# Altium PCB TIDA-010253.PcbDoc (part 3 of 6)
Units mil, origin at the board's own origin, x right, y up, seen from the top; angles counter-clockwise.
Board outline 5525 x 6695 mil, 4 copper layers (Top Layer, Signal Layer 1, Signal Layer 2, Bottom Layer), stack 61.2 mil thick; 522 components, 391 nets, 1722 pads, 1048 vias.
Unrouted connection lines stored in the file: 22.
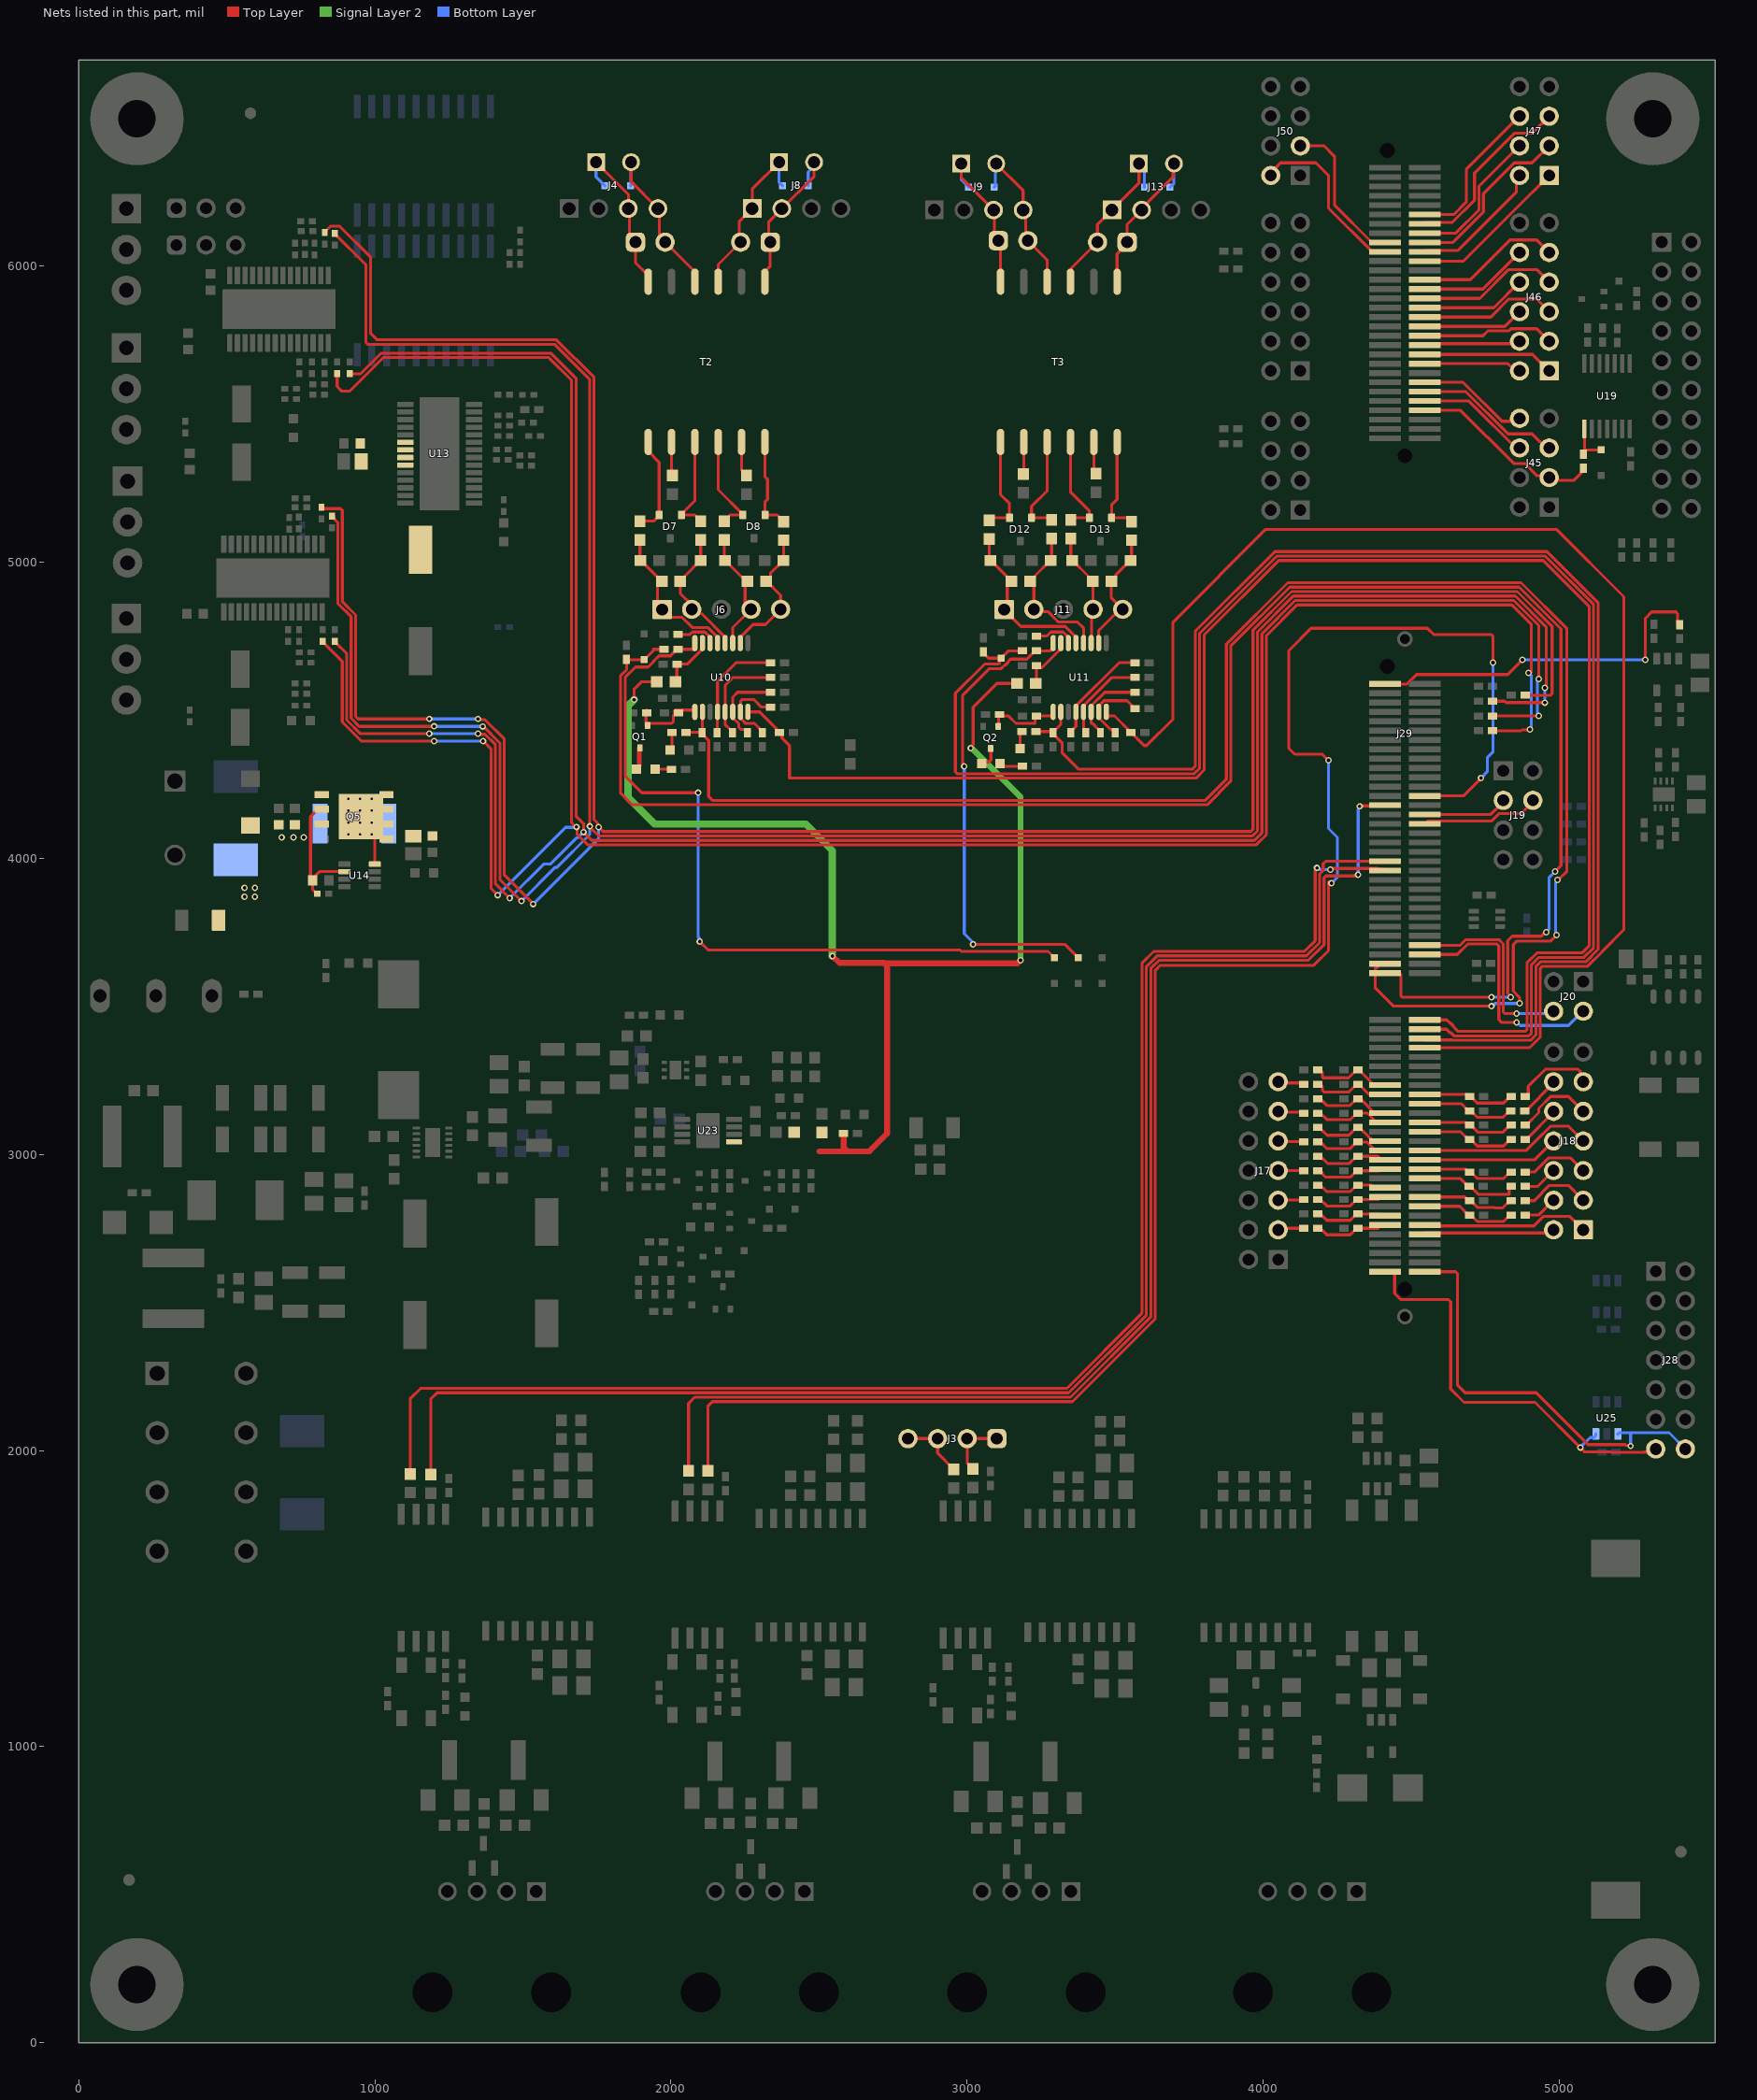
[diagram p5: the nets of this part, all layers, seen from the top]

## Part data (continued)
U28: library part CMP-0051906-3, "Automotive Catalog Dual Schmitt-Trigger Buffer, DCK0006A (SOT-SC70-6)", F @ Nom Voltage(Max)(Mhz)=150, Generic Part Number=SN74LVC2G17-Q1, ICC @ Nom Voltage(Max)(mA)=0.01, Manufacturer="Texas Instruments", Operating Temperature Range="-40 to 125 C", Rating=Automotive, tpd @ Nom Voltage(Max)(ns)=9.3,5.7,5.4,4.3, Voltage(Nom)(V)=1.8,2.5,3.3,5
U29: library part CMP-0035533-1, "Single Output LDO, 150 mA, Fixed 3.8 V Output, 2.7 to 10 V Input, with Low IQ, 5-pin SOT-23 (DBV), -40 to 125 degC, Green (RoHS & no Sb/Br)", Manufacturer="Texas Instruments"
U30: library part CMP-0089033-2, "Transformer Driver PMIC SOT-23-6", Manufacturer="Texas Instruments", Operating Temperature Range="-40°C to +125°C"
U31: library part CMP-0081937-2, "5-kVRMS Reinforced and Basic Isolated RS-485/RS-422 Transceiver With Robust-EMC, DW0016B (SOIC-16)", Alternate Manufacturer="Texas Instruments", Alternate PartNumber=ISO1410DW, Operating Temperature Range="-40 to 125 C"
U32: library part CMP-0087942-2, "Integrated Humidity and Temperature Digital Sensor", Manufacturer="Texas Instruments", Operating Temperature Range="-45°C to +150°C"
U33: library part CMP-0002019-2, "Asymmetrical TVS Diode for Extended Common-Mode RS-485, SOT-23", Manufacturer=Semtech, PartNumber=ESDS552, Supplier Part Number 1=SM712CT-ND
Y1: library part CMP-0004577-3, "Crystal, 32.768 kHz, 12.5pF, SMD", Frequency Stability=+/-20ppm, Frequency_Fixed=32.768kHz, Manufacturer=Epson, Supplier Part Number 1=SER2407CT-ND

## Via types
v1: diameter 22, hole 12, Top Layer to Bottom Layer, 944 vias
v2: diameter 19.68, hole 7.87, Top Layer to Bottom Layer, 76 vias
v3: diameter 19.68, hole 7.87, Top Layer to Bottom Layer, tented both sides, 16 vias
v4: diameter 22, hole 12, Top Layer to Bottom Layer, tented both sides, 12 vias

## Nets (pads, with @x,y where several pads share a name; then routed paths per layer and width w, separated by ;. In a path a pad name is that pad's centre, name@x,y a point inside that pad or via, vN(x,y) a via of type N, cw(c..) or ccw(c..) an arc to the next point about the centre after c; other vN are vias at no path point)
24V: C47.1 C48.1 C53.1 C59.1 Q5.5 Q5.6 Q5.7 Q5.8 Q5.9 R75.2 R84.2 U13.20 U13.21 U13.22 U13.23 U14.8 | length 104.1
  Top Layer w10: v2(990,4080) 1000,4070 U14.8@1000,3980
  other v2: 910,4080 950,4080 910,4120 950,4120 990,4120 910,4160 950,4160 990,4160 910,4200 950,4200 990,4200
24V_CONN: C50.1 C51.1 C52.1 D17.2 D36.2 F1.2 Q5.1 Q5.2 Q5.3 R75.1 R82.2 U14.2 | length 442.5
  Top Layer w10: C52.1@789.88,3925 789.88,3893.78 803.66,3880 R82.2@805.63,3880 ; Q5.2@820.5,4165 807.5,4165 782.5,4140 782.5,3927.38 784.88,3925 784.88,3925.98 813.31,3954.41 U14.2@897.64,3954.41
  other v1: 560,3870 595,3870 560,3900 595,3900 685,4070 725,4070 760,4070
"(9) HSEC_GPMC0_AD14": J29.169 J47.6 | length 521.8
  Top Layer w10: J29.169@4545,6173.35 4643.36,6173.35 4685,6214.99 4685,6325 J47.6@4865,6505
"(11) HSEC_GPMC0_AD0": J29.153 J46.10 | length 371.2
  Top Layer w10: J29.153@4545,5921.38 4741.38,5921.38 J46.10@4865,6045
"(11) HSEC_GPMC0_AD2": J29.155 J46.9 | length 493.4
  Top Layer w10: J29.155@4545,5952.87 4698.33,5952.87 4832.94,6087.48 4922.52,6087.48 J46.9@4965,6045
"(11) HSEC_GPMC0_AD4": J29.159 J47.1 | length 539.8
  Top Layer w10: J29.159@4545,6015.87 4675.79,6015.87 4847.4,6187.48 4847.48,6187.48 J47.1@4965,6305
"(13) HSEC_MII0_TXCLK": J29.129 J45.6 | length 389.8
  Top Layer w10: J29.129@4545,5543.43 4694.07,5543.43 4862.5,5375 J45.6@4865,5375
"(13) HSEC_MII0_TXD0": J29.131 J45.5 | length 502.8
  Top Layer w10: J29.131@4545,5574.92 4683.79,5574.92 4826.19,5432.52 4907.48,5432.52 J45.5@4965,5375
"(13) HSEC_MII0_TXD2": J29.133 J45.8 | length 374.4
  Top Layer w10: J29.133@4545,5606.42 4674.21,5606.42 4805.63,5475 J45.8@4865,5475
"(13) HSEC_MII1_TXCLK": J29.147 J46.5 | length 462.7
  Top Layer w10: J29.147@4545,5826.89 4768.1,5826.89 4828.69,5887.48 4922.52,5887.48 J46.5@4965,5845
"(13) HSEC_MII1_TXD0": J29.149 J46.8 | length 355.9
  Top Layer w10: J29.149@4545,5858.39 4778.39,5858.39 J46.8@4865,5945
"(13) HSEC_MII1_TXD2": J29.151 J46.7 | length 478
  Top Layer w10: J29.151@4545,5889.88 4731.1,5889.88 4828.69,5987.48 4922.52,5987.48 J46.7@4965,5945
"(14) HSEC_MII1_CRS": J29.139 J46.1 | length 443.2
  Top Layer w10: J29.139@4545,5700.91 4909.09,5700.91 J46.1@4965,5645
"(14) HSEC_MII1_RXCLK": J29.141 J46.4 | length 325.2
  Top Layer w10: J29.141@4545,5732.4 4549.84,5737.24 4857.24,5737.24 J46.4@4865,5745
"(14) HSEC_MII1_RXD0": J29.143 J46.3 | length 447.4
  Top Layer w10: J29.143@4545,5763.9 4741.32,5763.9 4757.81,5780.39 4829.19,5780.39 4836.27,5787.48 4922.52,5787.48 J46.3@4965,5745
"(14) HSEC_MII1_RXD2": J29.145 J46.6 | length 340.5
  Top Layer w10: J29.145@4545,5795.39 4815.39,5795.39 J46.6@4865,5845
"(14) HSEC_MII1_RXER": J29.137 J46.2 | length 330.1
  Top Layer w10: J29.137@4545,5669.41 4825.72,5669.41 4850.13,5645 J46.2@4865,5645
ADC0_AIN0: C109.1 J29.12 R183.1 | length 245.2
  Top Layer w10: R183.1@4188.62,2750 4192.56,2750 4214.37,2728.19 4292.87,2728.19 4314.68,2750 C109.1@4318.62,2750 4386.14,2750 4397.36,2761.22 J29.12@4411.14,2761.22
ADC0_AIN0_R: J17.3 R183.2 | length 98.4
  Top Layer w10: J17.3@4043.96,2742.8 J17.3@4048.96,2747.8 ; J17.3@4050,2750 R183.2@4141.38,2750
ADC0_AIN1: C110.1 J29.14 R184.1 | length 243
  Top Layer w10: R184.1@4188.62,2798.64 4192.56,2798.64 4214.37,2776.83 4292.87,2776.83 4314.68,2798.64 C110.1@4318.62,2798.64 4391.44,2798.64 4397.36,2792.72 J29.14@4411.14,2792.72
ADC0_AIN2: C111.1 J29.15 R185.1 | length 321.5
  Top Layer w10: J29.15@4545,2824.21 4663.23,2824.21 4692.44,2795 C111.1@4696.38,2795 4700.32,2795 4722.13,2773.19 4810.63,2773.19 4832.44,2795 R185.1@4836.38,2795
ADC0_AIN2_R: J18.4 R185.2 | length 117.1
  Top Layer w10: R185.2@4883.62,2795 4928.79,2795 4978.79,2845 J18.4@4980,2845
ADC0_AIN3: C112.1 J29.17 R186.1 | length 316.7
  Top Layer w10: J29.17@4545,2855.71 4680.07,2855.71 4692.44,2843.33 C112.1@4696.38,2843.33 4700.32,2843.33 4723.65,2820 4780.3,2820 4781.3,2819 4808.11,2819 4832.44,2843.33 R186.1@4836.38,2843.33
ADC0_AIN3_R: J18.3 R186.2 | length 238.5
  Top Layer w10: R186.2@4883.62,2843.33 4914.37,2843.33 4966.04,2895 5030,2895 J18.3@5080,2845
ADC1_AIN0: C118.1 J29.18 R187.1 | length 244.1
  Top Layer w10: R187.1@4188.62,2847.27 4192.56,2847.27 4214.37,2825.46 4292.87,2825.46 4314.68,2847.27 C118.1@4318.62,2847.27 4388.93,2847.27 4397.36,2855.71 J29.18@4411.14,2855.71
ADC1_AIN0_R: J17.5 R187.2 | length 97.3
  Top Layer w10: J17.5@4043.96,2842.8 J17.5@4045.09,2843.94 ; J17.5@4046.14,2846.14 4140.24,2846.14 R187.2@4141.38,2847.27
ADC1_AIN1: C119.1 J29.20 R188.1 | length 244.3
  Top Layer w10: R188.1@4188.62,2895.91 4192.56,2895.91 4214.47,2874 4292.78,2874 4314.68,2895.91 C119.1@4318.62,2895.91 4364.09,2895.91 4372.8,2887.2 J29.20@4411.14,2887.2
ADC1_AIN2: C120.1 J29.21 R189.1 | length 336.3
  Top Layer w10: J29.21@4545,2918.7 4664.03,2918.7 4691.06,2891.67 C120.1@4695,2891.67 4698.94,2891.67 4725.46,2865.14 4830,2865.14 4830,2885.29 R189.1@4836.38,2891.67
ADC1_AIN2_R: J18.6 R189.2 | length 118.5
  Top Layer w10: R189.2@4883.62,2891.67 4926.67,2891.67 J18.6@4980,2945
ADC1_AIN3: C121.1 J29.23 R190.1 | length 313.7
  Top Layer w10: J29.23@4545,2950.2 4682.24,2950.2 4692.44,2940 C121.1@4696.38,2940 4700.32,2940 4722.13,2918.19 4810.63,2918.19 4832.44,2940 R190.1@4836.38,2940
ADC1_AIN3_R: J18.5 R190.2 | length 233.6
  Top Layer w10: R190.2@4883.62,2940 4914.92,2940 4962.4,2987.48 5037.52,2987.48 J18.5@5080,2945
ADC2_AIN0: C122.1 J29.24 R191.1 | length 245.2
  Top Layer w10: R191.1@4188.62,2944.55 4192.56,2944.55 4199.37,2937.73 4199.37,2933.8 4210.43,2922.73 4292.87,2922.73 4314.68,2944.55 C122.1@4318.62,2944.55 4391.71,2944.55 4397.36,2950.2 J29.24@4411.14,2950.2
ADC2_AIN0_R: J17.7 R191.2 | length 96.6
  Top Layer w10: J17.7@4043.96,2942.8 J17.7@4044.18,2942.58 ; J17.7@4045.23,2944.77 4141.15,2944.77 R191.2@4141.38,2944.55
ADC2_AIN1: C123.1 J29.26 R192.1 | length 247.3
  Top Layer w10: R192.1@4188.62,2993.18 4192.56,2993.18 4216.74,2969 4290.5,2969 4314.68,2993.18 C123.1@4318.62,2993.18 4385.88,2993.18 4397.36,2981.69 J29.26@4411.14,2981.69
ADC2_AIN2: C124.1 J29.28 R193.1 | length 253.3
  Top Layer w10: R193.1@4188.62,3041.82 4192.56,3041.82 4215.38,3019 4291.87,3019 4314.68,3041.82 C124.1@4318.62,3041.82 4349.37,3041.82 4373.16,3018.03 4406.3,3018.03 J29.28@4411.14,3013.19
ADC2_AIN2_R: J17.9 R193.2 | length 97.7
  Top Layer w10: J17.9@4043.96,3042.8 J17.9@4045.55,3041.21 ; J17.9@4046.59,3043.41 4139.79,3043.41 R193.2@4141.38,3041.82
ADC2_AIN3: C125.1 J29.30 R194.1 | length 264.1
  Top Layer w10: R194.1@4188.62,3090.45 4188.62,3089.39 4194.37,3083.64 4195.43,3083.64 4215.08,3064 4288.23,3064 4314.68,3090.45 C125.1@4318.62,3090.45 4325.43,3083.64 4331.46,3083.64 4355,3060.11 4355,3060 4365.47,3049.53 4406.3,3049.53 J29.30@4411.14,3044.69
ADC3_AIN0: C131.1 J29.31 R195.1 | length 320.3
  Top Layer w10: J29.31@4545,3076.18 4666.26,3076.18 4692.44,3050 C131.1@4696.38,3050 4700.32,3050 4722.13,3028.19 4810.63,3028.19 4832.44,3050 R195.1@4836.38,3050
ADC3_AIN0_R: J18.10 R195.2 | length 137.2
  Top Layer w10: R195.2@4883.62,3050 4887.56,3050 4980,3142.44 J18.10@4980,3145
ADC3_AIN1: C132.1 J29.33 R196.1 | length 314.6
  Top Layer w10: J29.33@4545,3107.68 4683.1,3107.68 4692.44,3098.33 C132.1@4696.38,3098.33 4700.32,3098.33 4723.65,3075 4809.11,3075 4832.44,3098.33 R196.1@4836.38,3098.33
ADC3_AIN1_R: J18.9 R196.2 | length 265.5
  Top Layer w10: R196.2@4883.62,3098.33 4887.56,3098.33 4930,3140.77 4930,3155.08 4969.92,3195 5030,3195 J18.9@5080,3145
ADC3_AIN2: C133.1 J29.34 R197.1 | length 253.6
  Top Layer w10: R197.1@4188.62,3139.09 4192.56,3139.09 4214.37,3117.28 4294.25,3117.28 4316.06,3139.09 C133.1@4320,3139.09 4350.75,3139.09 4377.32,3112.52 4406.3,3112.52 J29.34@4411.14,3107.68
ADC3_AIN2_R: J17.11 R197.2 | length 88.8
  Top Layer w10: J17.11@4055,3145 4057.95,3142.05 4138.42,3142.05 R197.2@4141.38,3139.09
ADC3_AIN3: C134.1 J29.36 R198.1 | length 262.3
  Top Layer w10: R198.1@4188.62,3187.73 4192.56,3187.73 4216.29,3164 4290.96,3164 4314.68,3187.73 C134.1@4318.62,3187.73 4325.43,3180.92 4334.08,3180.92 4370.98,3144.02 4406.3,3144.02 J29.36@4411.14,3139.17
ADC4_AIN0: C144.1 J29.37 R226.1 | length 318
  Top Layer w10: J29.37@4545,3170.67 4668.44,3170.67 4692.44,3146.67 C144.1@4696.38,3146.67 4700.32,3146.67 4721.98,3125 4723.59,3125 4723.73,3124.86 4809.25,3124.86 4831.06,3146.67 R226.1@4835,3146.67
ADC4_AIN0_R: J18.12 R226.2 | length 141.1
  Top Layer w10: R226.2@4882.24,3146.67 4886.18,3146.67 4980,3240.49 J18.12@4980,3245
ADC4_AIN1: C145.1 J29.39 R227.1 | length 312.4
  Top Layer w10: J29.39@4545,3202.17 4685.28,3202.17 4692.44,3195 C145.1@4696.38,3195 4700.32,3195 4722.13,3173.19 4810.63,3173.19 4832.44,3195 R227.1@4836.38,3195
ADC4_AIN1_R: J18.11 R227.2 | length 283.1
  Top Layer w10: R227.2@4883.62,3195 4887.56,3195 4894.37,3201.81 4894.37,3229.37 4952.48,3287.48 5062.52,3287.48 5069.48,3280.52 5069.48,3255.52 J18.11@5080,3245
ADC4_AIN2: C146.1 J29.40 R228.1 | length 266.7
  Top Layer w10: R228.1@4188.62,3236.36 4192.56,3236.36 4199.37,3229.55 4199.37,3215.63 4205,3210 4288.32,3210 4314.68,3236.36 C146.1@4318.62,3236.36 4322.56,3236.36 4356.76,3202.17 J29.40@4411.14,3202.17
ADC4_AIN2_R: J17.13 R228.2 | length 90
  Top Layer w10: J17.13@4055,3245 4059.32,3240.68 4137.06,3240.68 R228.2@4141.38,3236.36
ADC4_AIN3: C147.1 J29.42 R229.1 | length 276.3
  Top Layer w10: R229.1@4188.62,3285 4192.56,3285 4199.37,3278.19 4199.37,3260.63 4201.83,3258.17 4287.86,3258.17 4314.68,3285 C147.1@4318.62,3285 4322.56,3285 4373.9,3233.66 J29.42@4411.14,3233.66
ADC_A0: J18.2 J29.9 | length 441.3
  Top Layer w10: J29.9@4545,2729.72 4549.84,2734.57 4969.57,2734.57 J18.2@4980,2745
ADC_A1: J18.1 J29.11 | length 568.1
  Top Layer w10: J29.11@4545,2761.22 4548.03,2758.19 4913.19,2758.19 4945,2790 5035,2790 J18.1@5080,2745
ADC_C0: J18.8 J29.25 | length 461.2
  Top Layer w10: J29.25@4545,2981.69 4916.69,2981.69 J18.8@4980,3045
ADC_C1: J18.7 J29.27 | length 589.8
  Top Layer w10: J29.27@4545,3013.19 4888.51,3013.19 4921.74,3046.41 4921.74,3046.81 4969.92,3095 5030,3095 J18.7@5080,3045
AM263X_CAN1_RX: J3.3 J3.4 R204.1 | length 226.4
  Top Layer w10: J3.4@2800,2040 J3.3@2900,2040 2900,1991.18 2954.17,1937.01 R204.1@2954.17,1936.02
AM263X_CAN1_TX: J3.1 J3.2 R36.1 | length 210.4
  Top Layer w10: R36.1@3019.17,1937.52 3019.17,1938.5 3000,1957.67 J3.2@3000,2040 J3.1@3100,2040
AM263X_CAN2_RX: J29.94 R25.1 | length 4369.4
  Top Layer w10: R25.1@2059.17,1931.89 2059.17,2159.17 2080,2180 3348.99,2180 3620,2451.01 3620,3627.43 3647.57,3655 4151.57,3655 4205,3708.43 4205,3934.14 4210.86,3940 4308.14,3940 4309.85,3941.7 4317.7,3941.7 v1(4320,3944) ; v1(4325,4175) 4326.77,4176.77 4409.37,4176.77 J29.94@4411.14,4178.54
  Bottom Layer w10: v1(4320,3944) 4320,4166.75 4325,4171.75 v1(4325,4175)
AM263X_CAN2_TX: J29.95 R23.1 | length 6245.4
  Top Layer w10: R23.1@2124.17,1931.89 2124.17,2149.17 2140,2165 3355.21,2165 3635,2444.79 3635,3621.21 3652.03,3638.24 4170.36,3638.24 4220,3687.88 4220,3920 v1@4235,3920 ; v1(4220,4330) 4199,4351 4106,4351 4085.86,4371.14 4085.86,4700.86 4161.11,4776.11 4553.89,4776.11 4575,4755 4769.14,4755 4775,4749.14 v1(4775,4660) ; J29.95@4545,4210.04 4675.04,4210.04 v1(4735,4270)
  Bottom Layer w10: v1(4220,4330) 4220,4100 4250,4070 4250,3935 v1(4230,3915) ; v1(4735,4270) 4756.15,4291.15 4756.15,4339.4 4775,4358.25 v1(4775,4660)
AM263X_UART0_RX: J29.163 J47.3 | length 591
  Top Layer w10: J29.163@4545,6078.86 4640.07,6078.86 4743.13,6181.92 4743.13,6243.21 4847.4,6347.48 4907.48,6347.48 J47.3@4965,6405
AM263X_UART0_TX: J29.164 J50.3 | length 517.9
  Top Layer w10: J50.3@4125,6405 4205,6405 4240,6370 4240,6205 4365,6080 4410,6080 J29.164@4411.14,6078.86
AM263X_UART1_RX: J29.161 J47.2 | length 453.1
  Top Layer w10: J29.161@4545,6047.36 4549.84,6052.2 4657.2,6052.2 4854.48,6249.48 4854.48,6294.48 J47.2@4865,6305
AM263X_UART1_TX: J29.162 J50.2 | length 597.8
  Top Layer w10: J50.2@4025,6305 4025,6314.14 4058.34,6347.48 4177.52,6347.48 4220,6305 4220,6195 4367.64,6047.36 J29.162@4411.14,6047.36
AM263X_UART2_RX: J29.165 J47.4 | length 488.9
  Top Layer w10: J29.165@4545,6110.35 4650.35,6110.35 4728.13,6188.13 4728.13,6268.13 J47.4@4865,6405
AM263X_UART2_TX: J29.167 J47.5 | length 623.9
  Top Layer w10: J29.167@4545,6141.85 4549.84,6146.69 4637.92,6146.69 4713.13,6221.9 4713.13,6313.21 4847.4,6447.48 4907.48,6447.48 J47.5@4965,6505
BQ0_BAT: C19.1 R38.1 U10.15 | length 189.1
  Top Layer w10: R38.1@2015,4595 2020,4600 C19.1@2020,4655 2054.66,4655 2106.02,4706.36 U10.15@2106.02,4726.14
BQ0_COMHN: C24.2 J6.2 R39.1 R40.1 U10.12 | length 452
  Top Layer w10: R40.1@2100,5075 C24.2@2100,5005 2099.02,5005 2046.18,4952.17 2046.18,4948.7 2032.48,4935 R39.1@2031.5,4935 2031.5,4893.38 2070,4854.87 J6.2@2070,4840 2084.87,4840 2099.09,4825.78 2102.93,4825.78 2182.8,4745.92 U10.12@2182.8,4726.14
BQ0_COMHN_ISO: D40.1 J4.4 J5.2 T2.10 | length 578.1
  Top Layer w10: J4.4@1865,6350 1865,6284.25 J4.4@1955.94,6193.31 1960.47,6188.78 J5.2@1960.47,6084.53 ; J5.2@1975.47,6084.53 J5.2@1980,6080 2077.65,5982.35 2077.65,5938.65 T2.10@2080.63,5935.67
  Bottom Layer w10: D40.1@1863.31,6270 1864.15,6270.85 1864.15,6349.15 J4.4@1865,6350
BQ0_COMHN_R: D7.1 R40.2 T2.3 | length 328.9
  Top Layer w10: T2.3@2080.63,5394.33 2080.63,5206.59 2034.8,5160.77 D7.1@2034.8,5158.8 2080.18,5158.8 2100,5138.98 R40.2@2100,5137.99
BQ0_COMHP: C20.1 J6.1 R37.1 R39.2 U10.13 | length 520.4
  Top Layer w10: R37.1@1895,5075 1895,5007.01 C20.1@1897.01,5005 1897.99,5005 1953.82,4949.17 1953.82,4948.7 R39.2@1967.52,4935 ; J6.1@1953.82,4842.82 1953.82,4921.3 R39.2@1967.52,4935 ; R39.2@1968.5,4935 R39.2@1967.52,4935 ; J6.1@1973.82,4842.82 J6.1@1970,4839 1995.53,4813.47 2036.46,4813.47 2071.22,4778.7 2124.43,4778.7 2133.13,4770 2157.2,4745.92 U10.13@2157.2,4726.14
BQ0_COMHP_ISO: D40.2 J4.3 J5.1 T2.12 | length 556.2
  Top Layer w10: J4.3@1746.89,6350 1855.94,6240.94 J4.3@1855.94,6193.31 1859.85,6189.4 J5.1@1859.85,6095.15 ; J5.1@1880,6080 1880,6010.31 1923.15,5967.17 T2.12@1923.15,5935.67
  Bottom Layer w10: J4.3@1746.89,6350 1746.89,6299.8 D40.2@1776.69,6270
BQ0_COMHP_R: D7.2 R37.2 T2.1 | length 336.2
  Top Layer w10: R37.2@1895,5137.99 1941.16,5137.99 1960,5156.83 D7.2@1960,5158.8 1960,5336.65 1923.15,5373.5 T2.1@1923.15,5405
BQ0_COMLN: C28.2 J6.4 R45.1 R51.1 U10.11 | length 414.2
  Top Layer w10: R51.1@2180,5075 2180,5007.01 C28.2@2182.01,5005 2182.99,5005 2239.29,4948.7 2244.8,4948.7 R45.1@2258.5,4935 2250,4926.5 J6.4@2250,4840 ; U10.11@2208.39,4726.14 2208.39,4778.39 J6.4@2270,4840
BQ0_COMLN_ISO: D41.1 J7.2 J8.1 T2.9 | length 601.4
  Top Layer w10: T2.9@2159.37,5935.67 2159.37,6004.37 J7.2@2235,6080 ; J7.2@2230,6065 2230,6149.25 J8.1@2274.06,6193.31 2274.06,6259.06 J8.1@2365,6350
  Bottom Layer w10: J8.1@2365,6350 2365,6281.69 D41.1@2376.69,6270
BQ0_COMLN_R: D8.2 R51.2 T2.4 | length 341.8
  Top Layer w10: T2.4@2159.37,5394.33 2159.37,5243.99 2242.6,5160.77 D8.2@2242.6,5158.8 2199.82,5158.8 2180,5138.98 R51.2@2180,5137.99
BQ0_COMLP: C26.1 J6.5 R43.1 R45.2 U10.10 | length 473.3
  Top Layer w10: U10.10@2233.98,4726.14 2233.98,4745.92 2276.75,4788.69 2318.69,4788.69 J6.5@2370,4840 2370,4887.48 R45.2@2322.48,4935 ; R45.2@2321.5,4935 R45.2@2322.48,4935 ; R43.1@2380,5073.5 C26.1@2380,5005 2379.02,5005 2336.18,4962.17 2336.18,4948.7 R45.2@2322.48,4935
BQ0_COMLP_ISO: D41.2 J7.1 J8.2 T2.7 | length 581.9
  Top Layer w10: T2.7@2316.85,5946.34 2316.85,5980.84 2335,5998.99 J7.1@2335,6065 ; J7.1@2330,6075 2330,6149.25 J8.2@2374.06,6193.31 2483.11,6302.36 J8.2@2483.11,6350 ; J7.1@2335,6080 J7.1@2335,6065 ; J7.1@2345,6075 J7.1@2335,6065
  Bottom Layer w10: D41.2@2463.31,6270 2463.31,6316.71 2483.11,6336.51 J8.2@2483.11,6350
BQ0_COMLP_R: D8.1 R43.2 T2.6 | length 315.8
  Top Layer w10: T2.6@2316.85,5394.33 2316.85,5288.04 2326,5278.89 2326,5211.3 2316.85,5202.15 2316.85,5159.35 D8.1@2317.4,5158.8 2358.68,5158.8 2380,5137.48 R43.2@2380,5136.5
BQ0_CT_H: C21.2 T2.2 | length 104.1
  Top Layer w10: T2.2@2001.89,5394.33 2001.89,5294.61 C21.2@2005,5291.5
BQ0_CT_L: C27.2 T2.5 | length 107.2
  Top Layer w10: T2.5@2238.11,5394.33 2238.11,5309.37 2253.11,5294.37 C27.2@2253.11,5293.39
BQ0_CVDD: C22.1 U10.14 | length 138.7
  Top Layer w10: C22.1@2023.62,4755 2063.92,4755 2072.62,4763.7 2113.84,4763.7 2131.61,4745.92 U10.14@2131.61,4726.14
BQ0_DVDD: C23.1 Q1.1 R50.1 U10.1 | length 260.9
  Top Layer w10: Q1.1@1915.59,4447.4 Q1.1@1915.59,4455 ; R50.1@1915.59,4498.03 Q1.1@1915.59,4455 ; R50.1@1918.62,4500 R50.1@1920.59,4498.03 ; C23.1@2009.68,4495 2012.87,4498.19 2014.68,4500 2018.62,4500 2076.87,4500 2080.43,4496.44 U10.1@2080.43,4493.86 ; C23.1@2018.62,4490 2014.68,4490 2007.87,4483.19 2007.87,4460.86 2002.02,4455 Q1.1@1915.59,4455
BQ0_FAULT: J29.60 R42.1 R53.1 U10.2 | length 5920.6
  Top Layer w10: R53.1@2050,4425 2104.65,4425 R42.1@2105.51,4424.13 ; U10.2@2106.02,4493.86 2105.51,4493.35 R42.1@2105.51,4424.13 ; J29.60@4411.14,3643.11 4397.36,3643.11 4385.71,3631.46 4383.38,3631.46 4377.52,3625.6 4377.52,3562.48 4440,3500 v1(4770,3500) ; v1(4865,3510) 4865,3530 4844,3551 4844,3707.46 4856.54,3720 4970,3720 v1(4990,3740) ; v1(4993.04,3926.96) 4996.29,3926.96 5025,3955.66 5025,4774.85 4869.85,4930 4082.72,4930 3875,4722.28 3875,4266.21 3803.79,4195 2140,4195 2126.81,4208.19 2126.81,4397.87 2105.51,4419.17 R42.1@2105.51,4424.13
  Bottom Layer w10: v1(4770,3500) 4773.25,3500 4782.25,3509 4864,3509 v1(4865,3510) ; v1@4986.52,3737.78 4987.7,3738.97 4987.7,3750.68 4986.52,3751.86 4986.52,3917.19
BQ0_GLED: D10.2 R52.1 | length 58.3
  Top Layer w10: D10.2@1946.5,4300 1997.76,4300 R52.1@2002.76,4305
BQ0_GLED_DRV: D10.1 Q1.3 | length 130.3
  Top Layer w10: D10.1@1883.5,4300 1895,4311.5 Q1.3@1895,4372.6 ; 1889.25,4320 1890,4320.75 Q1.3@1890,4372.6
BQ0_INH: D32.2 R44.2 U10.16 | length 2619.8
  Top Layer w10: U10.16@2080.43,4726.14 2080.43,4709.53 2075.9,4705 R44.2@2023.62,4705 2019.68,4705 1997.87,4683.19 1959.24,4683.19 1942.6,4666.54 1942.6,4664.83 1922.76,4645 1880,4645 1845,4610 1845,4277.87 1901.87,4221 v1(2091.86,4221) ; v1(2096.86,3717.85) 2124.71,3690 2975,3690 2980,3685 3273.31,3685 D32.2@3295,3663.31
  Bottom Layer w10: v1(2091.86,4221) 2091.86,3733.14 v1@2102.01,3722.99
BQ0_INH_L: C29.1 D9.1 J29.58 R44.1 | length 6307.5
  Top Layer w10: R44.1@1976.38,4705 1940,4705 1940,4700 D9.1@1910,4670 1851.38,4670 C29.1@1850,4671.38 1850,4636.21 1830,4616.21 1830,4218.79 1868.79,4180 3810,4180 3890,4260 3890,4716.07 4088.93,4915 4863.64,4915 5005,4773.64 5005,3975 v1(4985,3955) ; J29.58@4411.14,3611.61 4459.3,3611.61 4464.14,3606.77 4464.14,3535.86 4470,3530 v1(4770,3530) ; v1(4835,3530) 4835,3533.25 4825,3543.25 4825,3721.54 4840,3736.54 4938.29,3736.54 4951.75,3750 v1(4955,3750)
  Bottom Layer w10: v1(4770,3530) v1(4835,3530) ; v1(4955,3750) 4955,3751.86 4965,3761.86 4965,3935 v1(4985,3955)
BQ0_RLED: D11.1 R53.2 | length 62.4
  Top Layer w10: D11.1@1997.01,4365 2002.76,4370.75 R53.2@2002.76,4425
BQ0_SPI_CS: R49.2 R167.2 U10.7 | length 270.9
  Top Layer w10: R167.2@2309,4423.62 2309,4427.56 2281.56,4455 2250,4455 2250,4457.44 2233.98,4473.46 U10.7@2233.98,4493.86 2235.45,4495.33 2235.45,4530.45 2240.86,4535.86 2279.14,4535.86 2305,4510 R49.2@2336.38,4510
BQ0_SPI_MISO: R48.2 R164.2 U10.5 | length 335.5
  Top Layer w10: R164.2@2207,4423.62 2207,4427.56 2200.19,4434.37 2199.72,4434.37 2182.8,4451.3 U10.5@2182.8,4493.86 2182.8,4582.8 2210,4610 R48.2@2336.38,4610 ; R164.2@2209.17,4420.83 R164.2@2210,4420
BQ0_SPI_MOSI: R47.2 R163.2 U10.4 | length 379.7
  Top Layer w10: R163.2@2155,4423.62 2156.1,4424.72 2156.1,4492.76 U10.4@2157.2,4493.86 2157.2,4597.2 2220,4660 R47.2@2336.38,4660
BQ0_SPI_SCK: R46.2 R165.2 U10.6 | length 285.5
  Top Layer w10: R165.2@2258,4423.62 2258,4427.56 2251.19,4434.37 2235.63,4434.37 2228.81,4441.19 2228.81,4453.65 2208.39,4474.08 U10.6@2208.39,4493.86 2208.39,4543.39 2225,4560 R46.2@2336.38,4560 ; R165.2@2260,4420 R165.2@2260.83,4420.83
BQ0_SPIRDY: J29.55 R41.1 U10.8 | length 5615.1
  Top Layer w10: U10.8@2259.57,4493.86 2299.25,4493.86 2355.63,4437.48 2355.63,4431.81 2363.82,4423.62 2369.48,4423.62 2374.92,4418.19 2374.92,4404.77 2400,4379.69 2400,4270 3772.72,4270 3800,4297.28 3800,4753.35 4051.65,5005 4945.15,5005 5100,4850.15 5100,3703.64 5076.36,3680 4923.64,3680 4890,3646.36 4890,3420.86 4884.14,3415 4657.91,3415 4638.62,3434.29 4638.62,3436.62 4632.76,3442.48 4630.43,3442.48 4618.78,3454.13 J29.55@4545,3454.13
BQ1_BAT: C30.1 R55.1 U11.15 | length 213.3
  Top Layer w10: R55.1@3231.5,4590 3233.62,4592.13 C30.1@3233.62,4642.64 ; C30.1@3232.24,4641.26 C30.1@3233.62,4642.64 ; C30.1@3233.62,4650 C30.1@3233.62,4642.64 ; C30.1@3239.05,4643.07 3252.73,4643.07 3316.02,4706.36 U11.15@3316.02,4726.14 U11.15@3316.02,4745.92 ; C30.1@3239.05,4648.07 C30.1@3233.62,4642.64
BQ1_COMHN: C35.2 J11.2 R56.1 R57.1 U11.12 | length 519.3
  Top Layer w10: R57.1@3285,5078.5 3285,5008.44 C35.2@3281.5,5004.93 3280.51,5004.93 3227.68,4952.1 3227.68,4948.77 3213.98,4935.07 R56.1@3212.99,4935.07 3225,4923.06 J11.2@3225,4840 3232.56,4832.44 3272.48,4832.44 3307.4,4797.52 3372.48,4797.52 3392.8,4777.2 U11.12@3392.8,4726.14
BQ1_COMHN_ISO: D42.1 J9.4 J10.2 T3.10 | length 552.6
  Top Layer w10: J9.4@3098.11,6345 3189.06,6254.06 J9.4@3189.06,6188.31 3197.03,6180.33 3197.03,6092.97 J10.2@3205,6085 3270,6020 T3.10@3270,5946.34
  Bottom Layer w10: D42.1@3091.61,6265 3094.86,6268.25 3094.86,6341.75 J9.4@3098.11,6345
BQ1_COMHN_R: D12.1 R57.2 T3.3 | length 348.3
  Top Layer w10: T3.3@3270,5405 3270,5240 3217.4,5187.4 D12.1@3217.4,5149.37 3277.13,5149.37 R57.2@3285,5141.5
BQ1_COMHP: C31.1 J11.1 R54.1 R56.2 U11.13 | length 580.7
  Top Layer w10: R54.1@3075,5077.01 3075,5008.44 C31.1@3078.5,5004.93 3079.49,5004.93 3135.31,4949.11 3135.31,4948.77 R56.2@3149.02,4935.07 ; R56.2@3150,4935.07 R56.2@3149.02,4935.07 ; U11.13@3367.2,4726.14 3367.2,4745.92 3330.61,4782.52 3181.48,4782.52 J11.1@3125,4839 3135.31,4849.31 3135.31,4921.37 R56.2@3149.02,4935.07
BQ1_COMHP_ISO: D42.2 J9.3 J10.1 T3.12 | length 543.9
  Top Layer w10: J9.3@2980,6345 2980,6297.36 J9.3@3089.05,6188.31 3091.41,6185.95 3091.41,6098.59 J10.1@3105,6085 3112.52,6077.48 T3.12@3112.52,5946.34
  Bottom Layer w10: J9.3@2980,6345 2980,6290 D42.2@3005,6265
BQ1_COMHP_R: D12.2 R54.2 T3.1 | length 339.6
  Top Layer w10: R54.2@3075,5140 3084.37,5149.37 D12.2@3142.6,5149.37 3142.6,5197.4 3112.52,5227.48 T3.1@3112.52,5405
BQ1_COMLN: C39.2 J11.4 R62.1 R68.1 U11.11 | length 387.3
  Top Layer w10: R68.1@3350,5078.5 3350,5010 C39.2@3355,5005 3355.98,5005 3408.82,4952.17 3408.82,4948.7 3422.52,4935 R62.1@3423.5,4935 3425,4933.5 J11.4@3425,4840 3419.86,4834.86 3419.86,4727.62 U11.11@3418.39,4726.14
BQ1_COMLN_ISO: D43.1 J12.2 J13.1 T3.9 | length 582.1
  Top Layer w10: T3.9@3348.74,5946.34 3351.72,5949.32 3351.72,5991.72 3386.89,6026.89 J12.2@3440,6080 3440,6139.25 J13.1@3489.06,6188.31 3580,6279.25 J13.1@3580,6345
  Bottom Layer w10: J13.1@3580,6345 3598.39,6326.61 D43.1@3598.39,6265
BQ1_COMLN_R: D13.2 R68.2 T3.4 | length 347.9
  Top Layer w10: T3.4@3348.74,5405 3348.74,5236.26 3412.6,5172.4 D13.2@3412.6,5149.37 3357.87,5149.37 R68.2@3350,5141.5
BQ1_COMLP: C37.1 J11.5 R60.1 R62.2 U11.10 | length 432.3
  Top Layer w10: U11.10@3443.98,4726.14 3443.98,4768.98 3515,4840 J11.5@3525,4840 3486.5,4878.5 R62.2@3486.5,4935 3487.48,4935 3501.18,4948.7 3501.18,4955.67 3550.51,5005 C37.1@3551.5,5005 3555,5008.5 R60.1@3555,5073.5
BQ1_COMLP_ISO: D43.2 J12.1 J13.2 T3.7 | length 563.6
  Top Layer w10: T3.7@3506.22,5946.34 3506.22,6040.14 3540,6073.92 J12.1@3540,6080 3540,6139.25 J13.2@3589.06,6188.31 3589.06,6194.06 3695.08,6300.08 3695.08,6341.97 J13.2@3698.11,6345
  Bottom Layer w10: D43.2@3685,6265 3698.11,6278.11 J13.2@3698.11,6345
BQ1_COMLP_R: D13.1 R60.2 T3.6 | length 336.4
  Top Layer w10: T3.6@3506.22,5405 3506.22,5211.22 3487.4,5192.4 D13.1@3487.4,5149.37 3542.13,5149.37 R60.2@3555,5136.5
BQ1_CT_H: C32.2 T3.2 | length 109
  Top Layer w10: C32.2@3190.07,5296.5 3191.26,5297.69 T3.2@3191.26,5405
BQ1_CT_L: C38.2 T3.5 | length 110.1
  Top Layer w10: T3.5@3427.48,5405 3427.48,5305.58 C38.2@3435.07,5297.99
BQ1_CVDD: C33.1 U11.14 | length 140.8
  Top Layer w10: C33.1@3233.62,4750 3268.92,4750 3282.62,4763.7 3323.84,4763.7 3341.61,4745.92 U11.14@3341.61,4726.14
BQ1_DVDD: C34.1 Q2.1 R67.1 U11.1 | length 270.2
  Top Layer w10: Q2.1@3105.59,4437.4 3105.59,4476.97 3108.62,4480 3139.37,4480 3164.37,4455 3229.14,4455 3229.14,4475.52 C34.1@3233.62,4480 3286.87,4480 3290.43,4483.56 U11.1@3290.43,4493.86
BQ1_FAULT: J29.51 R59.1 R70.1 U11.2 | length 4718.8
  Top Layer w10: R70.1@3232.24,4427.31 3286.31,4427.31 R59.1@3290,4423.62 ; U11.2@3316.02,4493.86 3316.02,4451.3 3299.09,4434.37 3296.81,4434.37 3290,4427.56 R59.1@3290,4423.62 ; J29.51@4545,3391.14 4549.84,3386.3 4636.23,3386.3 4637.53,3385 4871.57,3385 4902.43,3385 4920,3402.57 4920,3433.43 4920,3633.93 4936.07,3650 5060,3650 5088.79,3650 5130,3691.21 5130,3707.22 5130,4862.57 4957.57,5035 4039.23,5035 3770,4765.77 3770,4309.71 3760.29,4300 3376.68,4300 3320.19,4356.49 3320.19,4389.5 3290,4419.68 R59.1@3290,4423.62
BQ1_GLED: D15.2 R69.1 | length 64.9
  Top Layer w10: D15.2@3121.5,4310 R69.1@3186.38,4310
BQ1_GLED_DRV: D15.1 Q2.3 | length 65.3
  Top Layer w10: D15.1@3048.5,4325 3073.5,4325 3080,4331.5 Q2.3@3080,4362.6
BQ1_INH: D33.2 R61.2 U11.16 | length 1618.2
  Top Layer w10: v1(2990,4310) 2990,4313.25 2985,4318.25 2985,4550 3075,4640 3115,4640 3128.19,4653.19 3130.95,4653.19 3136.81,4659.05 3136.81,4661.81 3146.81,4671.81 3201.5,4671.81 3229.68,4700 R61.2@3233.62,4700 3280.9,4700 3290.43,4709.53 U11.16@3290.43,4726.14 ; v1(3020,3709) 3329.31,3709 D33.2@3375,3663.31
  Bottom Layer w10: v1(2990,4310) 2990,3745 3020,3715 v1@3025,3715
BQ1_INH_L: C40.1 D14.1 J29.53 R61.1 | length 5423.6
  Top Layer w10: C40.1@3055,4696.38 3055,4692.44 3072.44,4675 D14.1@3115,4675 ; R61.1@3186.38,4700 3140,4700 D14.1@3115,4675 ; J29.53@4545,3422.64 4618.78,3422.64 4623.62,3417.8 4623.62,3416.84 4629.48,3410.98 4632.76,3410.98 4643.75,3400 4865.36,3400 4896.21,3400 4905,3408.79 4905,3439.64 4905,3640.15 4929.85,3665 5040,3665 5082.57,3665 5115,3697.43 5115,3713.43 5115,4856.36 4951.36,5020 4045.44,5020 3785,4759.56 3785,4303.49 3766.51,4285 2965.86,4285 2960,4290.86 2960,4556.21 3058.79,4655 3106.47,4655 3109.66,4658.19 3109.66,4669.66 D14.1@3115,4675
BQ1_RLED: D16.1 R70.2 | length 60
  Top Layer w10: D16.1@3178.5,4370 3178.5,4420.82 R70.2@3185,4427.31
BQ1_SPI_CS: R66.2 R172.2 U11.7 | length 261.8
  Top Layer w10: R172.2@3500,4423.62 3500,4427.56 3493.19,4434.37 3483.68,4434.37 3443.98,4474.08 3443.98,4513.64 3461.76,4531.42 3477.16,4531.42 3539.96,4531.42 3555.63,4515.75 3555.63,4511.81 3562.44,4505 R66.2@3566.38,4505
BQ1_SPI_MISO: R65.2 R169.2 U11.5 | length 306.5
  Top Layer w10: R169.2@3400,4423.62 3400,4427.56 3392.8,4434.76 U11.5@3392.8,4493.86 3392.8,4513.64 3489.16,4610 R65.2@3566.38,4610
BQ1_SPI_MOSI: R64.2 R168.2 U11.4 | length 356.9
  Top Layer w10: R168.2@3350,4423.62 3350,4427.56 3367.2,4444.76 U11.4@3367.2,4493.86 3367.2,4513.64 3513.57,4660 R64.2@3566.38,4660
BQ1_SPI_SCK: R63.2 R170.2 U11.6 | length 272.6
  Top Layer w10: R170.2@3450,4423.62 3450,4427.56 3422.32,4455.24 3418.39,4455.24 U11.6@3418.39,4493.86 3418.39,4513.64 3464.75,4560 R63.2@3566.38,4560
BQ1_SPIRDY: J29.49 R58.1 U11.8 | length 4488.4
  Top Layer w10: U11.8@3469.57,4493.86 3469.57,4483.72 3473.13,4480.16 3497.4,4480.16 3550,4427.56 3552.13,4427.56 3556.81,4422.87 3556.81,4420.75 3565.43,4412.13 3565.95,4412.13 3571.81,4406.27 3571.81,4405.75 3597.56,4380 3605.84,4380 3695,4469.16 3695,4796.84 4008.16,5110 4989.71,5110 5217,4882.71 5217,3758.21 5145,3686.21 5145,3685 5095,3635 4942.28,3635 4935,3627.72 4935,3396.36 4898.29,3359.65 J29.49@4545,3359.65
BQ_12V: C103.1 R38.2 R55.2 R137.2 R146.1 U23.1 | length 4232.5
  Top Layer w10: v1(1875,4535) 1875,4570 1900,4595 R38.2@1952.01,4595 ; v1@3015,4371.5 3014.3,4372.2 3014.3,4377.04 3020,4382.75 3020,4510 3100,4590 R55.2@3168.5,4590
  Top Layer w20: 2499.99,3010 2594.99,3010 ; v1(2545,3669) 2545.54,3669 2568.61,3645.93 2718.27,3645.93 2729.99,3634.22 2729.99,3070 2669.99,3010 2594.99,3010 ; R146.1@2582.74,3070 2582.74,3022.24 2594.99,3010 ; 2724.04,3645 3169.45,3645 3179.45,3655 v1(3179.99,3655)
  Signal Layer 2 w20: v1@3015,4371.5 3180,4206.5 v1(3179.99,3655)
  Signal Layer 2 w25: v1(1875,4535) 1855,4515 1855,4205 1945,4115 2455,4115 2545,4025 v1(2545,3669)
  other v1: 3012,4371.5
C2000_UARTB_RX: J20.4 J29.63 | length 673.3
  Top Layer w10: J29.63@4545,3706.1 4664.89,3706.1 4683.79,3725 4795.36,3725 4810,3710.36 4810,3705.36 4810,3480.86 4815.86,3475 4843.33,3475
  Bottom Layer w10: v1(4855,3475) 4970,3475 J20.4@4980,3485
C2000_UARTB_TX: J20.2 J29.61 | length 830.2
  Top Layer w10: J29.61@4545,3674.61 4654.61,3674.61 4690,3710 4789.14,3710 4795,3704.14 4795,3455 4805,3445 v1(4855,3445)
  Bottom Layer w10: v1(4855,3445) 4856.86,3445 4866.86,3435 5030,3435 J20.2@5080,3485
CAN0_RX: J29.80 R12.1 | length 5127.4
  Top Layer w10: R12.1@1119.17,1921.02 1119.17,2174.17 1155,2210 3336.57,2210 3590,2463.43 3590,3645 3630,3685 4139.14,3685 4175,3720.86 4175,3957.66 4181,3963.66 v1(4181,3966.91) ; v1(4226,3961) 4229.25,3961 4233.25,3965 4386.66,3965 4388.75,3962.91 4406.3,3962.91 J29.80@4411.14,3958.07
  Bottom Layer w10: v1(4181,3966.91) 4184.25,3966.91 4190.16,3961 v1(4226,3961)
CAN0_TX: J29.82 R10.1 | length 5067
  Top Layer w10: R10.1@1189.17,1919.02 1189.17,2174.17 1210,2195 3342.78,2195 3605,2457.22 3605,3633.64 3641.36,3670 4145.36,3670 4190,3714.64 4190,3946.21 4202,3958.21 4202,3980.71 4210.86,3989.57 J29.82@4411.14,3989.57
CONT_SPI_CS: R114.1 R115.1 R182.2 | length 9389.4
  Top Layer w10: R114.1@826.34,5180 884.14,5180 890,5174.14 890,4866.21 935,4821.21 935,4478.43 943.43,4470 v1@1180,4470 ; R115.1@831.02,6112.01 831.02,6113.98 850.86,6133.81 881.19,6133.81 985,6030 985,5772.88 1007.88,5750 1612.85,5750 1740,5622.85 1740,4130 1752.7,4117.3 1752.7,4107.3 1770,4090 3957.14,4090 3965,4097.86 3965,4769.85 4095.15,4900 4857.43,4900 4975,4782.43 4975,4555 4970,4550 R182.2@4883.62,4550 ; v1(1348.81,4470) 1351.1,4467.7 1371.14,4467.7 1437.07,4401.77 1437.07,3942.93 v1(1535,3845)
  Bottom Layer w10: v1(1183.81,4470) v1(1348.81,4470) ; v1(1535,3845) 1755,4065 v1(1755,4105)
CONT_SPI_MISO: R107.1 R109.1 R179.2 | length 8542.4
  Top Layer w10: R107.1@865,4732.64 865,4730.67 905,4690.67 905,4466.01 951.01,4420 v1(1183.81,4420) v1@1189.42,4420 ; R109.1@915,5635.31 952.09,5635.31 1021.78,5705 1594.21,5705 1680,5619.21 1680,4140 1705.19,4114.81 1705.19,4088.99 v1(1704.34,4088.14) ; v1(1348.81,4420) 1351.1,4417.7 1372.05,4417.7 1407.07,4382.68 1407.07,3912.93 v1(1455,3865) ; v1@1704.34,4086.42 1706.06,4086.42 1732.48,4060 3969.57,4060 3995,4085.43 3995,4757.43 4107.57,4870 4845,4870 4930,4785 v1(4930,4605) ; R179.2@4773.62,4480 v1(4930,4480)
  Bottom Layer w10: v1(1183.81,4420) v1(1348.81,4420) ; v1(1455,3865) 1569.61,3979.61 1592.33,3979.61 1680.68,4067.96 1684.16,4067.96 v1(1704.34,4088.14) ; v1(4930,4480) 4930,4483.25 4925,4488.25 4925,4596.75 4930,4601.75 v1(4930,4605)
CONT_SPI_MOSI: R110.1 R112.1 R178.2 | length 8652.1
  Top Layer w10: R110.1@823.82,4732.64 823.82,4730.67 890,4664.49 890,4459.79 954.79,4395 v1(1200.05,4395) ; R112.1@872.5,5635.63 872.5,5592.5 888.57,5576.43 914.42,5576.43 1027.99,5690 1587.99,5690 1664,5613.99 1664,4119.49 1683.08,4100.41 1683.08,4079.7 1717.78,4045 3975.78,4045 4010,4079.22 4010,4751.21 4113.79,4855 4838.79,4855 4905,4788.79 v1@4905,4627.74 ; v1(1365.05,4395) 1365.97,4395 1392.07,4368.89 1392.07,3897.93 v1(1415,3875) v1@1415,3871.75 ; R178.2@4773.62,4430 4870,4430 4872.87,4432.87 4897.87,4432.87 v1(4900,4435)
  Bottom Layer w10: v1(1200.05,4395) v1(1365.05,4395) ; v1(1415,3875) 1643.82,4103.82 1681.89,4103.82 v1@1684.19,4106.11 ; v1(4895,4625) 4905,4615 4905,4443.25 4900,4438.25 v1(4900,4435)
  other v1: 1680.78,4105.3
CONT_SPI_SCK: R104.1 R105.1 R180.2 | length 9343.6
  Top Layer w10: R104.1@859.84,5156.32 859.84,5148.19 875,5133.03 875,4860 920,4815 920,4472.22 947.22,4445 v1(1200.05,4445) ; R105.1@865,6109.69 865,6107.72 970,6002.72 970,5740.86 975.86,5735 1606.63,5735 1725,5616.63 1725,4105.3 1755.3,4075 3963.36,4075 3980,4091.64 3980,4763.64 4101.36,4885 4851.21,4885 4955,4781.21 v1@4955,4570 ; v1(1364.6,4444.54) 1366.42,4444.54 1422.07,4388.89 1422.07,3927.93 v1(1495,3855) ; R180.2@4773.62,4530 4814.68,4530 4819.68,4525 v1(4950,4525)
  Bottom Layer w10: v1(1200.05,4445) 1200.28,4444.77 1364.37,4444.77 v1(1364.6,4444.54) ; v1(1495,3855) 1608.15,3968.15 1614.04,3968.15 1725.34,4079.44 1725.34,4104.36 v1@1726.19,4105.21 ; v1(4950,4525) v1(4950,4575)
  other v1: 1726.19,4107.21
DRV_FAULT_ALL: D24.2 R121.1 U19.8 | length 151
  Top Layer w10: R121.1@5080,5363.62 5080,5367.56 R121.1@5084.41,5371.97 ; U19.8@5083.82,5449.53 5084.41,5448.94 R121.1@5084.41,5371.97 ; R121.1@5084.41,5364.21 5085,5363.62 R121.1@5085,5359.68 ; D24.2@5140,5378.31 5090.75,5378.31 R121.1@5084.41,5371.97
DRV_FAULT_ALL_L: J29.127 J45.3 R121.2 | length 657.6
  Top Layer w10: J29.127@4545,5511.93 4665.99,5511.93 4845.4,5332.52 4882.48,5332.52 4923.93,5291.07 4948.93,5291.07 4965,5275 5047.56,5275 5085,5312.44 R121.2@5085,5316.38
EMU0: J28.13 J29.2 U25.6 | length 1466.7
  Top Layer w10: J29.2@4411.14,2603.74 4438.23,2603.74 4443.07,2598.9 4443.07,2530.19 4463.57,2509.69 4624.46,2509.69 4632.5,2501.64 4632.5,2207.5 4677.5,2162.5 4917.5,2162.5 v1(5070,2010) 5085,1995 5174.12,1995 5175.12,1994 5284,1994 5284.48,1994.48 5314.48,1994.48 J28.13@5325,2005
  Bottom Layer w10: v1(5070,2010) 5103.47,2043.47 5115.79,2043.47 5122.6,2050.28 U25.6@5122.6,2055.87 ; J28.13@5316.66,2005 J28.13@5325,2005
EMU1: J28.14 J29.1 U25.4 | length 1470.4
  Top Layer w10: J29.1@4545,2603.74 4649.14,2603.74 4655,2597.88 4655,2221.21 4681.21,2195 4921.21,2195 5096.21,2020 5221.18,2020 5223.89,2017.3 5237.7,2017.3 v1(5240,2015) ; J28.14@5420,2010 5425,2010 J28.14@5425,2005
  Bottom Layer w10: U25.4@5196.2,2054.67 U25.4@5197.4,2055.87 5201.54,2060 5235,2060 ; v1(5240,2015) 5240,2055 5235,2060 ; J28.14@5425,2005 5370,2060 5235,2060
EXT_I2C1_GPIO: J19.4 J29.89 | length 402.9
  Top Layer w10: J29.89@4545,4115.55 4554.45,4125 4770,4125 4795.02,4150.02 4870.02,4150.02 J19.4@4915,4195
EXT_I2C2_GPIO: J19.3 J29.91 | length 295.7
  Top Layer w10: J29.91@4545,4147.05 4767.05,4147.05 4805,4185 4805,4195 J19.3@4815,4195
EXT_RESET: J29.120 R153.2 | length 1203.1
  Top Layer w10: J29.120@4411.14,4587.99 4484.92,4587.99 4516.93,4620 4825,4620 v1(4875,4670) ; v1@5290,4671.5 5290,4810 5311.38,4831.38 5392.76,4831.38 5398.62,4825.52 R153.2@5398.62,4788.62
  Bottom Layer w10: v1@4880,4670 v1(5290,4670)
